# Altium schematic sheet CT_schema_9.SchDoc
size 147 x 119 mm
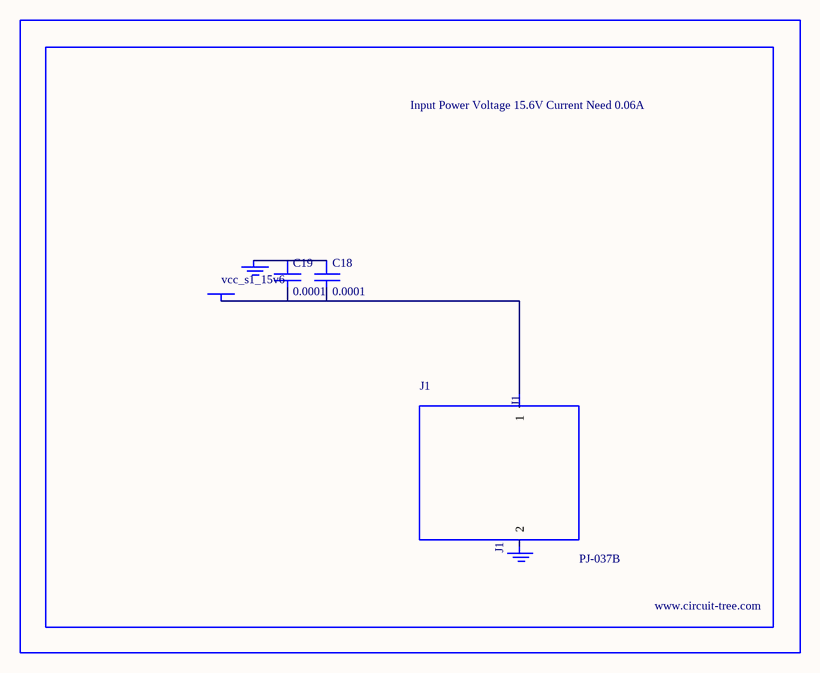
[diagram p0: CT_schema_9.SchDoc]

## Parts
BORDER8  (no value)
C18  0.0001  [EXV-9H]
C19  0.0001  [EXV-9H]
GND_INSTANCE_8_0  (no value)
GND_INSTANCE_8_1  (no value)
J1  PJ-037B  [PJ-037B_PACKAGE]
POWER_INSTANCE_8_0  vcc_s1_15v6

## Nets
NetC18_1: C18.1 C19.1 GND_INSTANCE_8_0.0(GND)
NetC18_2: C18.2 C19.2 J1.1 POWER_INSTANCE_8_0.0(PWR)

Not connected (* = marked no-connect by the designer): GND_INSTANCE_8_1 0(GND); J1 2

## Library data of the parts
BORDER8 = BORDER_PAGE8
C18 C19 = EDK107M035A9HAA
GND_INSTANCE_8_0 GND_INSTANCE_8_1 = GND
POWER_INSTANCE_8_0 = PWR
